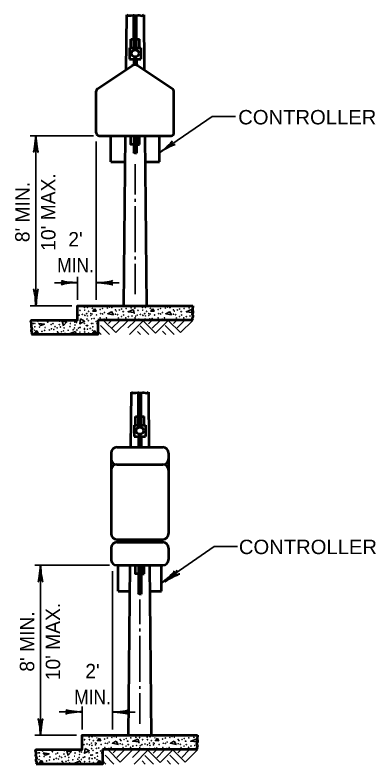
# Model space of a CAD drawing. Extents: x -1 to 679, y 1 to 441.
# Drawn here: x 407.9 to 470.7, y 103.2 to 233.3 of the extents above; entities that cross this region are included whole.
import ezdxf
from ezdxf.enums import TextEntityAlignment as Align

# ---------------------------------------------------------------- set-up
doc = ezdxf.new("R2010")
doc.units = 0
doc.layers.add('1', color=7, linetype='Continuous', lineweight=35)

msp = doc.modelspace()

# ---------------------------------------------------------------- linework, layer by layer
at = {"layer": '1', "lineweight": 53}
for p, q in [((427.306, 233.289), (427.211, 223.746)), ((428.556, 227.607), (428.556, 233.253)), ((429.056, 227.607), (429.056, 233.151)), ((430.306, 233.289), (430.4, 223.746)), ((428.056, 227.607), (428.056, 229.107)), ((428.056, 229.107), (428.556, 229.107)), ((429.056, 229.107), (429.556, 229.107)), ((429.556, 227.607), (429.556, 229.107)), ((427.806, 227.607), (429.806, 227.607)), ((427.806, 227.607), (427.806, 225.607)), ((429.806, 227.607), (429.806, 225.607)), ((427.806, 225.607), (429.806, 225.607)), ((428.556, 225.607), (428.556, 224.576)), ((429.056, 225.607), (429.056, 224.576)), ((422.278, 220.458), (428.251, 224.439)), ((429.36, 224.439), (435.333, 220.458)), ((422.056, 212.809), (422.056, 220.042)), ((435.556, 212.809), (435.556, 220.042)), ((422.556, 212.309), (435.056, 212.309)), ((424.556, 207.809), (424.556, 212.309)), ((427.098, 212.309), (426.806, 182.789)), ((428.556, 212.309), (428.556, 209.309)), ((429.056, 212.309), (429.056, 209.309)), ((429.556, 210.809), (429.556, 212.309)), ((430.513, 212.309), (430.806, 182.789)), ((433.056, 207.809), (433.056, 212.309)), ((428.556, 211.559), (429.056, 211.559)), ((429.056, 210.809), (429.556, 210.809)), ((424.556, 207.809), (427.053, 207.809)), ((430.558, 207.809), (433.056, 207.809)), ((438.806, 180.289), (422.306, 180.289)), ((428.113, 167.747), (428.019, 158.204)), ((429.363, 162.066), (429.363, 167.711)), ((429.863, 162.066), (429.863, 167.609)), ((431.113, 167.747), (431.207, 158.204)), ((428.863, 162.066), (428.863, 163.566)), ((428.863, 163.566), (429.363, 163.566)), ((429.863, 163.566), (430.363, 163.566)), ((430.363, 162.066), (430.363, 163.566)), ((428.613, 162.066), (430.613, 162.066)), ((428.613, 162.066), (428.613, 160.066)), ((430.613, 162.066), (430.613, 160.066)), ((428.613, 160.066), (430.613, 160.066)), ((429.363, 160.066), (429.363, 158.204)), ((429.863, 160.066), (429.863, 158.204)), ((425.613, 158.204), (433.613, 158.204)), ((424.613, 157.204), (424.613, 143.204)), ((434.613, 157.204), (434.613, 143.204)), ((425.613, 155.204), (433.613, 155.204)), ((425.613, 142.204), (433.613, 142.204)), ((425.863, 141.704), (425.863, 142.204)), ((429.363, 142.204), (429.363, 141.704)), ((429.863, 142.204), (429.863, 141.704)), ((433.363, 141.704), (433.363, 142.204)), ((424.613, 140.704), (424.613, 138.704)), ((425.613, 141.704), (433.613, 141.704)), ((434.613, 140.704), (434.613, 138.704)), ((425.613, 137.704), (433.613, 137.704)), ((425.863, 133.204), (425.863, 137.704)), ((427.905, 137.704), (427.613, 108.184)), ((429.363, 137.704), (429.363, 132.704)), ((429.363, 136.954), (429.863, 136.954)), ((429.863, 137.704), (429.863, 132.704)), ((430.363, 136.204), (430.363, 137.704)), ((431.321, 137.704), (431.613, 108.184)), ((433.363, 133.204), (433.363, 137.704)), ((429.863, 136.204), (430.363, 136.204)), ((425.863, 133.204), (427.861, 133.204)), ((431.365, 133.204), (433.363, 133.204)), ((439.613, 105.684), (423.113, 105.684))]:
    msp.add_line(p, q, dxfattribs=at)
at = {"layer": '1'}
for p, q in [((421.556, 212.309), (410.556, 212.309)), ((411.556, 212.309), (411.556, 182.789)), ((422.056, 211.309), (422.056, 183.789)), ((428.829, 202.08), (428.829, 207.371)), ((428.829, 200.83), (428.829, 201.33)), ((428.829, 192.08), (428.829, 200.08)), ((428.829, 190.83), (428.829, 191.33)), ((428.829, 184.789), (428.829, 190.08)), ((418.806, 183.789), (418.806, 187.789)), ((414.806, 186.789), (418.806, 186.789)), ((422.056, 186.789), (426.056, 186.789)), ((417.806, 182.789), (410.556, 182.789)), ((422.093, 179.706), (422.306, 179.681)), ((422.306, 179.493), (422.093, 179.706)), ((423.286, 180.249), (425.426, 178.109)), ((424.706, 180.249), (424.186, 179.729)), ((426.146, 180.249), (424.826, 178.929)), ((427.566, 180.249), (425.426, 178.109)), ((428.846, 180.249), (427.526, 178.929)), ((430.266, 180.249), (427.806, 177.789)), ((429.342, 180.289), (429.373, 180.505)), ((429.413, 180.486), (429.757, 180.289)), ((430.166, 180.249), (432.366, 178.049)), ((431.686, 180.249), (431.126, 179.669)), ((433.126, 180.249), (431.746, 178.869)), ((434.546, 180.249), (432.366, 178.049)), ((434.546, 180.249), (436.686, 178.109)), ((435.966, 180.249), (435.446, 179.729)), ((437.406, 180.249), (436.086, 178.929)), ((438.826, 180.249), (436.686, 178.109)), ((422.306, 178.389), (422.906, 177.789)), ((422.766, 179.349), (424.326, 177.789)), ((429.226, 178.329), (429.766, 177.789)), ((429.686, 179.289), (431.202, 177.789)), ((433.566, 178.389), (434.166, 177.789)), ((434.026, 179.349), (435.586, 177.789)), ((414.633, 177.945), (414.347, 177.789)), ((414.707, 177.789), (414.593, 177.965)), ((424.363, 137.704), (411.363, 137.704)), ((412.363, 137.704), (412.363, 108.184)), ((424.863, 136.704), (424.863, 109.184)), ((429.637, 127.476), (429.637, 131.767)), ((429.637, 126.226), (429.637, 126.726)), ((429.637, 117.476), (429.637, 125.476)), ((429.637, 116.226), (429.637, 116.726)), ((429.637, 110.184), (429.637, 115.476)), ((415.621, 112.23), (419.621, 112.23)), ((419.613, 109.184), (419.613, 113.184)), ((424.81, 112.21), (428.81, 112.21)), ((418.613, 108.184), (411.363, 108.184)), ((424.093, 105.644), (426.233, 103.504)), ((425.513, 105.644), (424.993, 105.124)), ((426.953, 105.644), (425.633, 104.324)), ((428.373, 105.644), (426.233, 103.504)), ((429.653, 105.644), (428.333, 104.324)), ((431.073, 105.644), (428.613, 103.184)), ((430.15, 105.684), (430.181, 105.901)), ((430.221, 105.881), (430.564, 105.684)), ((430.973, 105.644), (433.173, 103.444)), ((432.493, 105.644), (431.933, 105.064)), ((433.933, 105.644), (432.553, 104.264)), ((435.353, 105.644), (433.173, 103.444)), ((435.353, 105.644), (437.493, 103.504)), ((436.773, 105.644), (436.253, 105.124)), ((438.213, 105.644), (436.893, 104.324)), ((439.633, 105.644), (437.493, 103.504)), ((422.901, 105.101), (423.113, 105.076)), ((423.113, 104.888), (422.901, 105.101)), ((423.573, 104.744), (425.133, 103.184)), ((430.493, 104.684), (432.009, 103.184)), ((434.833, 104.744), (436.393, 103.184)), ((415.441, 103.341), (415.154, 103.184)), ((415.514, 103.184), (415.401, 103.361)), ((423.113, 103.784), (423.713, 103.184)), ((430.033, 103.724), (430.573, 103.184)), ((434.373, 103.784), (434.973, 103.184))]:
    msp.add_line(p, q, dxfattribs=at)
at = {"layer": '1', "lineweight": 53}
for points in [[(427.306, 233.289), (427.563, 233.211), (428.095, 233.203), (428.111, 233.203), (428.525, 233.25), (428.635, 233.258), (429.159, 233.187), (429.339, 233.25), (429.534, 233.258), (430.019, 233.164), (430.306, 233.289)], [(428.556, 210.809), (428.056, 210.809), (428.056, 212.309)], [(428.556, 209.309), (428.626, 209.386), (428.746, 209.335), (428.775, 209.335), (428.872, 209.335), (428.906, 209.346), (428.969, 209.346), (429.027, 209.3), (429.056, 209.309)], [(410.806, 177.789), (410.897, 177.921), (410.902, 178.133), (410.793, 178.379), (410.809, 178.521), (410.924, 178.793), (410.798, 179.137), (410.771, 179.295), (410.826, 179.633), (410.809, 179.791), (410.695, 180.004), (410.806, 180.289), (418.806, 180.289), (418.806, 182.789), (438.853, 182.789)], [(438.853, 182.789), (438.786, 182.133), (438.84, 181.795), (438.813, 181.637), (438.687, 181.293), (438.802, 181.021), (438.818, 180.879), (438.709, 180.633), (438.715, 180.421), (438.806, 180.289)], [(422.306, 180.289), (422.306, 177.789), (410.806, 177.789)], [(428.113, 167.747), (428.37, 167.669), (428.902, 167.661), (428.918, 167.661), (429.333, 167.708), (429.442, 167.716), (429.966, 167.645), (430.146, 167.708), (430.342, 167.716), (430.827, 167.622), (431.113, 167.747)], [(429.363, 136.204), (428.863, 136.204), (428.863, 137.704)], [(429.363, 132.704), (429.433, 132.781), (429.554, 132.73), (429.582, 132.73), (429.68, 132.73), (429.714, 132.741), (429.777, 132.741), (429.834, 132.695), (429.863, 132.704)], [(411.613, 103.184), (411.704, 103.316), (411.709, 103.529), (411.6, 103.774), (411.617, 103.916), (411.731, 104.188), (411.606, 104.532), (411.579, 104.69), (411.633, 105.028), (411.617, 105.186), (411.502, 105.399), (411.613, 105.684), (419.613, 105.684), (419.613, 108.184), (439.661, 108.184)], [(439.661, 108.184), (439.593, 107.528), (439.648, 107.19), (439.62, 107.032), (439.495, 106.688), (439.609, 106.416), (439.626, 106.274), (439.517, 106.029), (439.522, 105.816), (439.613, 105.684)], [(423.113, 105.684), (423.113, 103.184), (411.613, 103.184)]]:
    msp.add_lwpolyline(points, dxfattribs=at)
at = {"layer": '1'}
for points in [[(433.157, 209.451), (442.217, 215.663), (446.27, 215.663)], [(421.813, 182.266), (421.433, 181.865), (422.013, 181.826), (421.813, 182.225)], [(431.893, 182.266), (431.513, 181.865), (432.093, 181.826), (431.893, 182.225)], [(424.713, 181.745), (424.053, 181.386), (425.033, 181.206), (424.673, 181.766)], [(428.533, 182.125), (427.593, 181.745), (428.633, 181.625), (428.533, 182.085)], [(434.793, 181.745), (434.133, 181.386), (435.113, 181.206), (434.753, 181.766)], [(438.613, 182.125), (437.673, 181.745), (438.713, 181.625), (438.613, 182.085)], [(416.353, 179.285), (416.113, 180.085), (416.893, 179.925), (416.333, 179.326)], [(419.333, 180.486), (420.033, 180.085), (419.173, 179.665), (419.293, 180.505)], [(411.733, 178.465), (411.353, 178.065), (411.933, 178.025), (411.733, 178.425)], [(418.453, 178.326), (417.513, 177.945), (418.553, 177.826), (418.453, 178.285)], [(421.813, 178.465), (421.433, 178.065), (422.013, 178.025), (421.813, 178.425)], [(433.49, 134.737), (442.55, 140.948), (446.603, 140.948)], [(422.621, 107.661), (422.241, 107.261), (422.821, 107.221), (422.621, 107.621)], [(425.521, 107.141), (424.861, 106.781), (425.841, 106.601), (425.481, 107.161)], [(429.341, 107.521), (428.401, 107.141), (429.441, 107.021), (429.341, 107.481)], [(432.701, 107.661), (432.321, 107.261), (432.901, 107.221), (432.701, 107.621)], [(435.601, 107.141), (434.941, 106.781), (435.921, 106.601), (435.561, 107.161)], [(439.421, 107.521), (438.481, 107.141), (439.521, 107.021), (439.421, 107.481)], [(417.161, 104.681), (416.921, 105.481), (417.701, 105.321), (417.141, 104.721)], [(420.141, 105.881), (420.841, 105.481), (419.981, 105.061), (420.101, 105.901)], [(412.541, 103.861), (412.161, 103.461), (412.741, 103.421), (412.541, 103.821)], [(419.261, 103.721), (418.321, 103.341), (419.361, 103.221), (419.261, 103.681)], [(422.621, 103.861), (422.241, 103.461), (422.821, 103.421), (422.621, 103.821)]]:
    msp.add_lwpolyline(points, dxfattribs=at)
for points in [[(412.013, 179.706), (413.053, 179.585), (412.373, 179.345)], [(412.821, 105.101), (413.861, 104.981), (413.181, 104.741)]]:
    msp.add_lwpolyline(points, close=True, dxfattribs=at)
at = {"layer": '1', "lineweight": 53}
for centre in [(428.817, 226.618), (429.625, 161.076)]:
    msp.add_circle(centre, 0.625, dxfattribs=at)
at = {"layer": '1'}
for centre in [(418.966, 182.702), (420.013, 182.469), (420.026, 182.636), (420.516, 182.522), (421.007, 182.649), (421.372, 182.336), (422.711, 182.124), (423.161, 182.296), (423.97, 182.389), (424.367, 182.583), (424.765, 182.455), (425.322, 182.742), (426.461, 182.217), (426.554, 182.742), (427.243, 182.323), (428.131, 182.416), (428.343, 182.729), (428.767, 182.376), (429.046, 182.702), (430.093, 182.469), (430.106, 182.636), (430.596, 182.522), (431.087, 182.649), (431.452, 182.336), (432.791, 182.124), (433.241, 182.296), (434.05, 182.389), (434.447, 182.583), (434.845, 182.455), (435.402, 182.742), (436.541, 182.217), (436.634, 182.742), (437.323, 182.323), (438.211, 182.416), (438.423, 182.729), (419.098, 181.156), (419.217, 182.005), (419.628, 181.275), (420.052, 182.018), (420.079, 181.13), (420.397, 181.421), (420.503, 181.023), (420.728, 181.832), (421.086, 181.434), (421.099, 181.116), (421.319, 181.355), (422.101, 181.183), (422.817, 181.408), (423.161, 181.368), (423.479, 181.607), (425.388, 182.058), (425.388, 181.315), (425.547, 181.845), (425.772, 181.222), (426.064, 182.058), (426.435, 180.891), (426.687, 181.753), (426.74, 181.753), (426.806, 181.169), (427.614, 180.904), (428.264, 180.997), (428.661, 181.487), (428.9, 180.984), (429.178, 181.156), (429.297, 182.005), (429.708, 181.275), (430.132, 182.018), (430.159, 181.13), (430.477, 181.421), (430.583, 181.023), (430.808, 181.832), (431.166, 181.434), (431.179, 181.116), (431.399, 181.355), (432.181, 181.183), (432.897, 181.408), (433.241, 181.368), (433.559, 181.607), (435.468, 182.058), (435.468, 181.315), (435.627, 181.845), (435.852, 181.222), (436.144, 182.058), (436.515, 180.891), (436.767, 181.753), (436.82, 181.753), (436.886, 181.169), (437.694, 180.904), (438.344, 180.997), (411.159, 179.709), (411.385, 179.724), (411.928, 180.056), (413.625, 179.95), (414.221, 179.539), (414.499, 180.175), (414.539, 179.685), (415.679, 180.109), (417.561, 179.698), (418.343, 179.95), (418.634, 179.883), (419.986, 179.738), (420.45, 180.467), (420.675, 180.175), (421.239, 179.709), (421.258, 180.52), (421.465, 179.724), (421.677, 180.573), (422.008, 180.056), (422.737, 180.679), (423.426, 180.467), (423.824, 180.679), (424.99, 180.347), (425.891, 180.652), (427.203, 180.679), (428.728, 180.361), (428.794, 180.666), (430.53, 180.467), (431.338, 180.52), (431.757, 180.573), (432.817, 180.679), (433.506, 180.467), (433.904, 180.679), (435.07, 180.347), (435.971, 180.652), (437.283, 180.679), (410.927, 178.849), (411.292, 178.536), (411.385, 179.128), (412.193, 179.088), (412.631, 178.324), (413.081, 178.496), (413.187, 179.008), (413.89, 178.589), (414.287, 178.783), (414.685, 178.655), (414.884, 179.141), (415.242, 178.942), (415.308, 178.258), (415.639, 179.512), (415.825, 179.088), (415.984, 178.258), (416.381, 178.417), (416.474, 178.942), (417.163, 178.523), (417.495, 179.154), (418.051, 178.616), (418.263, 178.929), (418.356, 179.433), (418.687, 178.576), (418.966, 178.902), (419.244, 179.022), (420.013, 178.669), (420.026, 178.836), (420.052, 178.218), (420.317, 179.34), (420.516, 178.722), (420.543, 179.34), (421.007, 178.849), (421.372, 178.536), (421.465, 179.128), (422.273, 179.088), (415.467, 178.045), (416.607, 177.953), (416.66, 177.953), (419.217, 178.205), (420.728, 178.032), (419.773, 108.097), (420.833, 108.031), (421.814, 108.044), (425.175, 107.978), (426.129, 108.137), (427.362, 108.137), (429.151, 108.124), (429.853, 108.097), (430.913, 108.031), (431.894, 108.044), (435.255, 107.978), (436.209, 108.137), (437.442, 108.137), (439.231, 108.124), (420.025, 107.4), (420.436, 106.671), (420.82, 107.864), (420.86, 107.413), (421.204, 106.816), (421.324, 107.917), (421.536, 107.227), (421.894, 106.83), (422.127, 106.75), (422.18, 107.731), (423.518, 107.519), (423.624, 106.803), (423.969, 107.691), (423.969, 106.763), (424.287, 107.002), (424.777, 107.784), (425.572, 107.85), (426.195, 107.453), (426.195, 106.71), (426.354, 107.241), (426.871, 107.453), (427.269, 107.612), (427.494, 107.148), (427.547, 107.148), (428.051, 107.718), (428.939, 107.811), (429.469, 106.883), (429.575, 107.771), (430.105, 107.4), (430.516, 106.671), (430.9, 107.864), (430.94, 107.413), (431.284, 106.816), (431.404, 107.917), (431.616, 107.227), (431.974, 106.83), (432.207, 106.75), (432.26, 107.731), (433.598, 107.519), (433.704, 106.803), (434.049, 107.691), (434.049, 106.763), (434.367, 107.002), (434.857, 107.784), (435.652, 107.85), (436.275, 107.453), (436.275, 106.71), (436.434, 107.241), (436.951, 107.453), (437.349, 107.612), (437.574, 107.148), (437.627, 107.148), (438.131, 107.718), (439.019, 107.811), (412.736, 105.451), (415.307, 105.57), (416.486, 105.504), (419.906, 106.551), (420.886, 106.525), (421.257, 105.862), (421.311, 106.419), (421.483, 105.57), (421.907, 106.511), (422.066, 105.915), (422.484, 105.968), (422.816, 105.451), (422.908, 106.578), (423.545, 106.074), (424.234, 105.862), (424.631, 106.074), (425.798, 105.743), (426.58, 106.618), (426.699, 106.047), (427.242, 106.286), (427.613, 106.564), (428.011, 106.074), (428.422, 106.299), (429.071, 106.392), (429.535, 105.756), (429.601, 106.061), (429.707, 106.379), (429.986, 106.551), (430.966, 106.525), (431.337, 105.862), (431.391, 106.419), (431.987, 106.511), (432.146, 105.915), (432.564, 105.968), (432.988, 106.578), (433.625, 106.074), (434.314, 105.862), (434.711, 106.074), (435.878, 105.743), (436.66, 106.618), (436.779, 106.047), (437.322, 106.286), (437.693, 106.564), (438.091, 106.074), (438.502, 106.299), (439.151, 106.392), (411.734, 104.244), (411.966, 105.104), (412.192, 105.119), (412.192, 104.523), (413.001, 104.483), (413.995, 104.404), (414.432, 105.345), (415.029, 104.934), (415.095, 104.178), (415.347, 105.08), (415.691, 104.536), (416.049, 104.337), (416.447, 104.907), (416.632, 104.483), (417.282, 104.337), (418.302, 104.549), (418.368, 105.093), (419.071, 104.324), (419.15, 105.345), (419.164, 104.828), (419.442, 105.279), (419.773, 104.297), (420.051, 104.417), (420.794, 105.133), (420.82, 104.064), (420.833, 104.231), (421.125, 104.735), (421.324, 104.117), (421.35, 104.735), (421.814, 104.244), (422.046, 105.104), (422.272, 105.119), (422.272, 104.523), (423.081, 104.483), (412.1, 103.931), (413.438, 103.719), (413.889, 103.891), (414.697, 103.984), (415.492, 104.05), (416.115, 103.653), (416.274, 103.441), (416.791, 103.653), (417.189, 103.812), (417.414, 103.348), (417.467, 103.348), (417.971, 103.918), (418.859, 104.011), (419.495, 103.971), (420.025, 103.6), (420.86, 103.613), (421.536, 103.427), (422.18, 103.931)]:
    msp.add_circle(centre, 0.0265, dxfattribs=at)
at = {"layer": '1', "lineweight": 53}
for centre, radius, start, end in [((428.806, 223.607), 1, 56.30808, 123.69007), ((422.556, 220.042), 0.5, 123.69239, 180), ((435.056, 220.042), 0.5, 0, 56.30661), ((422.556, 212.809), 0.5, 180, 270), ((435.056, 212.809), 0.5, 270, 0), ((425.613, 157.204), 1, 90, 180), ((433.613, 157.204), 1, 0, 90), ((425.613, 156.204), 1, 180, 270), ((433.613, 156.204), 1, 270, 0), ((425.613, 154.204), 1, 90, 180), ((433.613, 154.204), 1, 0, 90), ((425.613, 143.204), 1, 180, 270), ((433.613, 143.204), 1, 270, 0), ((425.613, 140.704), 1, 90, 180), ((433.613, 140.704), 1, 0, 90), ((425.613, 138.704), 1, 180, 270), ((433.613, 138.704), 1, 270, 0)]:
    msp.add_arc(centre, radius, start, end, dxfattribs=at)
at = {"layer": '1'}
for centre, start, end in [((423.267, 182.808), 226.35082, 313.64918), ((433.347, 182.808), 226.35082, 313.64918), ((438.847, 182.376), 61.61934, 241.7845), ((418.82, 180.984), 237.37076, 122.62924), ((438.741, 181.487), 32.83014, 287.06312), ((412.604, 180.281), 162.01481, 17.98519), ((417.402, 180.308), 223.9797, 316.0203), ((417.919, 180.281), 162.01481, 17.98519), ((422.684, 180.281), 17.98519, 162.01481), ((427.482, 180.308), 316.0203, 223.9797), ((427.999, 180.281), 17.98519, 162.01481), ((432.764, 180.281), 17.98519, 162.01481), ((437.562, 180.308), 316.0203, 223.9797), ((438.079, 180.281), 17.98519, 162.01481), ((413.399, 177.807), 318.30023, 221.69977), ((424.075, 108.204), 226.35082, 313.64918), ((434.155, 108.204), 226.35082, 313.64918), ((439.549, 106.883), 32.83014, 287.06312), ((439.655, 107.771), 61.61934, 241.7845), ((413.412, 105.676), 162.01481, 17.98519), ((418.209, 105.703), 223.9797, 316.0203), ((418.726, 105.676), 162.01481, 17.98519), ((419.627, 106.379), 237.37076, 122.62924), ((423.492, 105.676), 17.98519, 162.01481), ((428.289, 105.703), 316.0203, 223.9797), ((428.806, 105.676), 17.98519, 162.01481), ((433.572, 105.676), 17.98519, 162.01481), ((438.369, 105.703), 316.0203, 223.9797), ((438.886, 105.676), 17.98519, 162.01481), ((414.207, 103.202), 318.30023, 221.69977)]:
    msp.add_arc(centre, 0.0265, start, end, dxfattribs=at)
at = {"layer": '1', "lineweight": 40}
for centre, major_axis, ratio, start_param, end_param in [((411.344, 211.189), (0.176, 1.756), 0.07063, 3.1407148, 5.41811), ((411.344, 211.189), (0.176, 1.756), 0.07063, 3.1407148, 5.41811), ((411.832, 211.218), (-0.156, 1.786), 0.122415, 0.8963533, 3.1415927), ((411.832, 211.218), (-0.156, 1.786), 0.122415, 0.8963533, 3.1415927), ((433.9, 210.296), (-1.384, -1.139), 0.122415, 0.8963533, 3.1415927), ((433.9, 210.296), (-1.384, -1.139), 0.122415, 0.8963533, 3.1415927), ((434.2, 209.91), (1.548, 0.848), 0.07063, 6.2823074, 8.5597026), ((434.2, 209.91), (1.548, 0.848), 0.07063, 6.2823074, 8.5597026), ((417.714, 186.513), (1.786, 0.156), 0.122415, 0.8963533, 3.1415927), ((417.714, 186.513), (1.786, 0.156), 0.122415, 0.8963533, 3.1415927), ((417.685, 187.001), (1.756, -0.176), 0.07063, 3.1407148, 5.41811), ((417.685, 187.001), (1.756, -0.176), 0.07063, 3.1407148, 5.41811), ((423.176, 186.578), (-1.756, 0.176), 0.07063, 3.1407148, 5.41811), ((423.176, 186.578), (-1.756, 0.176), 0.07063, 3.1407148, 5.41811), ((423.147, 187.066), (-1.786, -0.156), 0.122415, 0.8963533, 3.1415927), ((423.147, 187.066), (-1.786, -0.156), 0.122415, 0.8963533, 3.1415927), ((411.279, 183.88), (0.156, -1.786), 0.122415, 0.8963533, 3.1415927), ((411.767, 183.91), (-0.176, -1.756), 0.07063, 3.1407148, 5.41811), ((412.151, 136.584), (0.176, 1.756), 0.07063, 3.1407148, 5.41811), ((412.151, 136.584), (0.176, 1.756), 0.07063, 3.1407148, 5.41811), ((412.639, 136.613), (-0.156, 1.786), 0.122415, 0.8963533, 3.1415927), ((412.639, 136.613), (-0.156, 1.786), 0.122415, 0.8963533, 3.1415927), ((434.246, 135.58), (-1.384, -1.139), 0.122415, 0.8963533, 3.1415927), ((434.708, 135.691), (-1.384, -1.139), 0.122415, 0.8963533, 3.1415927), ((434.546, 135.194), (1.548, 0.848), 0.07063, 6.2823074, 8.5597026), ((435.008, 135.305), (1.548, 0.848), 0.07063, 6.2823074, 8.5597026), ((418.521, 111.962), (1.786, 0.156), 0.122415, 0.8963533, 3.1415927), ((418.492, 112.45), (1.756, -0.176), 0.07063, 3.1407148, 5.41811), ((425.901, 112.486), (-1.786, -0.156), 0.122415, 0.8963533, 3.1415927), ((425.901, 112.486), (-1.786, -0.156), 0.122415, 0.8963533, 3.1415927), ((425.931, 111.999), (-1.756, 0.176), 0.07063, 3.1407148, 5.41811), ((425.931, 111.999), (-1.756, 0.176), 0.07063, 3.1407148, 5.41811), ((412.087, 109.276), (0.156, -1.786), 0.122415, 0.8963533, 3.1415927), ((412.575, 109.305), (-0.176, -1.756), 0.07063, 3.1407148, 5.41811)]:
    msp.add_ellipse(centre, major_axis=major_axis, ratio=ratio, start_param=start_param, end_param=end_param, dxfattribs=at)

# ---------------------------------------------------------------- texts
at = {"layer": '1', "width": 1.05}
for p in [(446.717, 214.286), (446.832, 139.645)]:
    msp.add_text('CONTROLLER', height=2.5, dxfattribs=at).set_placement(p)
at = {"layer": '1'}
for s, p in [("10' MAX.", (414.965, 199.067)), ("8' MIN.", (410.465, 199.067)), ("10' MAX.", (415.772, 124.462)), ("8' MIN.", (411.272, 124.462))]:
    msp.add_text(s, height=2.5, rotation=90, dxfattribs=at).set_placement(p, align=Align.CENTER)
for p in [(418.445, 193.085), (421.396, 118.079)]:
    msp.add_text("2'", height=2.5, dxfattribs=at).set_placement(p, align=Align.CENTER)
at = {"layer": '1', "width": 0.9}
for p in [(418.445, 188.585), (421.396, 113.579)]:
    msp.add_text('MIN.', height=2.5, dxfattribs=at).set_placement(p, align=Align.CENTER)

doc.saveas('drawing.dxf')
